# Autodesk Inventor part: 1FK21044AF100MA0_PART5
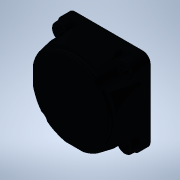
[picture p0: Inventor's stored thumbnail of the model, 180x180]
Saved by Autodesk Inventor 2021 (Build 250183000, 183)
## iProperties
Created: 2025-04
Part Number: 1FK21044AF100MA0_PART5
Material: Generic
Catalog Web Link: www.3dfindit.com
Description: -Servo synchronous motor
Document SubType Name: Modeling
Designer: psAdmin
Mass: 3.92604 g
Surface Area: 17.9521 cm^2
Volume: 3.92604 cm^3
Density: 1 g/cm^3
Appearance: PSOLRGB-48-56-69
Category: PARTsolutions
Title: 1FK21044AF100MA0_PART5
Author: Cadenas PARTsolutions
Comments: Servo synchronous motor
Sending System: PARTsolutions
Preprocessor: ST-DEVELOPER v19.3
PSOL_IDENT_0: {$CADENAS_DATA/23d-libs/siemens_ag/_cat_/ec/e4/1fk21044af100ma0.prj},213 {VTYP=3D},{NB=1FK21044AF100
PSOL_IDENT_1: MA0_PART5},{LINA=1FK21044AF100MA0_PART5},{NN=1FK21044AF100MA0_PART5},{NOPRJ=TRUE},{DATE=19.08.2025 1
PSOL_IDENT_2: 4:01:05},{GEOMDATE=30.07.2025 02:01:01},{VERSION=},{LINEID=10},{WBVAR=},{WBNUMERIC=}  {NB=1FK21044AF
PSOL_IDENT_3: 100MA0_PART5},{LINA=1FK21044AF100MA0_PART5},{KT=DUMMY},{PREVIEW=../../../_pool_/cb/72/p_d211_xx_0043
PSOL_IDENT_4: 4j.png},{DESCSHORT=SIMOTICS S-1FK2 HD, SINAMICS S210 3AC 400V-480V, 1.27 Nm, 3000 rpm},{DESCLONG=SIM
PSOL_IDENT_5: OTICS S-1FK2 HD servo motor M0=1.27 Nm; PN = 0.4 kW at nN=3000 rpm (380-480 V); PN = 0.2 kW at nN=15
PSOL_IDENT_6: 00 rpm (200-240 V); with holding brake; degree of protection IP64; cylindrical shaft D19x40mm; absol
PSOL_IDENT_7: ute encoder 22-bit + 12-bit multiturn (encoder AM22DQC); with OCC interface; plug size M17, rotatabl
PSOL_IDENT_8: e; SIMOTICS S-1FK2 servomotorfor a wide range of uses in industrial environments. SIMOTICS S‑1FK2 se
PSOL_IDENT_9: rvomotors are compact synchronous motors with a high dynamic performance that set themselves apart a
PSOL_IDENT_10: s a result of their high power density, degree of protection and overload capability. The motors are
PSOL_IDENT_11: available in two variants: as High Dynamic variant (highest dynamic performance as a result of the
PSOL_IDENT_12: low intrinsic moment of inertia for applications demanding a high dynamic performance with low moved
PSOL_IDENT_13: masses) - and as Compact variant (precise and stable closed-loop control for medium up to large mov
PSOL_IDENT_14: ed masses as a result of a medium intrinsic moment of inertia). SIMOTICSS‑1FK2 servomotors fully exp
PSOL_IDENT_15: loit their strengths in a system with the SINAMICSS210 frequency converter and simple connection usi
PSOL_IDENT_16: ng the one cable connection (OCC). Advantages include the short control and positioning times, fast
PSOL_IDENT_17: and precise correction of disturbing quantities as well as stable control with a high dynamic perfor
PSOL_IDENT_18: mance. The servo motors can be configured to address a wide range of requirements. For example with
PSOL_IDENT_19: and without holding brake, IP64 or IP65 degree of protection, singleturn or multiturn absolute encod
PSOL_IDENT_20: ers - to name just a few. Further, the servomotors are available in different shaft heights extendin
PSOL_IDENT_21: g from 20 to 100. A shaft sealing ring is available to achieve an IP65 degree of protection and for
PSOL_IDENT_22: subsequent mounting at the motor or as spare part. SIMOTICS - the optimum motor for each and every m
PSOL_IDENT_23: otion control application.},{INTNO=195125043275},{SUPPLIERALTNO=1FK2104-4AF10-0MA0},{MANUID=1FK21044
PSOL_IDENT_24: AF100MA0},{MANUNAME=Siemens},{MANUTYPEDESC=Synchronous motor 1FK2-HD 1.27 NM},{AAU732=SIMOTICS},{AAO
PSOL_IDENT_25: 057=S-1FK2},{AAU734=SIMOTICS S-1FK2 HD servo motor M0=1.27 Nm; PN = 0.4 kW at nN=3000 rpm (380-480 V
PSOL_IDENT_26: ); PN = 0.2 kW at nN=1500 rpm (200-240 V); with holding brake; degree of protection IP64; cylindrica
PSOL_IDENT_27: l shaft D19x40mm; absolute encoder 22-bit + 12-bit multiturn (encoder AM22DQC); with OCC interface;
PSOL_IDENT_28: plug size M17, rotatable;},{AAW338=Synchronous motor 1FK2-HD 1.27 NM},{AAO742=SIMOTICS},{AAO663=4042
PSOL_IDENT_29: 948694015},{NOCUPEROU=1},{PRICEQUANTITY=1},{QUANTITYMIN=1},{QUANTITYINT=1},{CTN=85015100},{COO=DE},{
PSOL_IDENT_30: AAO676=1FK2104-4AF10-0MA0},{AAO677=Siemens AG},{ORDERUNIT=C62},{CONTENTUNIT=C62}
NB: 1FK21044AF100MA0_PART5
NT: Servo synchronous motor
NBSYN: $MANUID._PART5
LINA: 1FK21044AF100MA0_PART5
CATALOG: SIEMENS
PREVIEW: ../../../_pool_/cb/72/p_d211_xx_00434j.png
DESCSHORT: SIMOTICS S-1FK2 HD, SINAMICS S210 3AC 400V-480V, 1.27 Nm, 3000 rpm
DESCLONG: SIMOTICS S-1FK2 HD servo motor M0=1.27 Nm; PN = 0.4 kW at nN=3000 rpm (380-480 V); PN = 0.2 kW at nN=1500 rpm (200-240 V); with holding brake; degree of protect
INTNO: 195125043275
SUPPLIERALTNO: 1FK2104-4AF10-0MA0
MANUID: 1FK21044AF100MA0
MANUNAME: Siemens
MANUTYPEDESC: Synchronous motor 1FK2-HD 1.27 NM
AAU732: SIMOTICS
AAO057: S-1FK2
AAU734: SIMOTICS S-1FK2 HD servo motor M0=1.27 Nm; PN = 0.4 kW at nN=3000 rpm (380-480 V); PN = 0.2 kW at nN=1500 rpm (200-240 V); with holding brake; degree of protect
AAW338: Synchronous motor 1FK2-HD 1.27 NM
AAO742: SIMOTICS
AAO663: 4042948694015.0
NOCUPEROU: 1
PRICEQUANTITY: 1
QUANTITYMIN: 1
QUANTITYINT: 1
CTN: 85015100
COO: DE
ARTICLENO: 1FK21044AF100MA0_PART5
BOMINFO: 1FK21044AF100MA0_PART5
CREATOR: CADENAS GmbH
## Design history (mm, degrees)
feature "2025_04_17_15_33_01_0611"
body "Solid1"
